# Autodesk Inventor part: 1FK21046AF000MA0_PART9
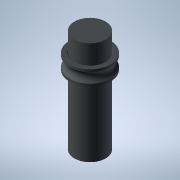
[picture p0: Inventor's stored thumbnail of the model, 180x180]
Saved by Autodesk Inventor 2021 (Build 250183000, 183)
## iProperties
Created: 2025-04
Part Number: 1FK21046AF000MA0_PART9
Material: Generic
Catalog Web Link: www.3dfindit.com
Description: -Servo synchronous motor
Document SubType Name: Modeling
Designer: psAdmin
Mass: 18.6788 g
Surface Area: 52.316 cm^2
Volume: 18.6788 cm^3
Density: 1 g/cm^3
Appearance: PSOLRGB-212-217-219
Category: PARTsolutions
Title: 1FK21046AF000MA0_PART9
Author: Cadenas PARTsolutions
Comments: Servo synchronous motor
Sending System: PARTsolutions
Preprocessor: ST-DEVELOPER v19.3
PSOL_IDENT_0: {$CADENAS_DATA/23d-libs/siemens_ag/_cat_/1c/1f/1fk21046af000ma0.prj},213 {VTYP=3D},{NB=1FK21046AF000
PSOL_IDENT_1: MA0_PART9},{LINA=1FK21046AF000MA0_PART9},{NN=1FK21046AF000MA0_PART9},{NOPRJ=TRUE},{DATE=19.08.2025 1
PSOL_IDENT_2: 4:00:28},{GEOMDATE=30.07.2025 02:02:08},{VERSION=},{LINEID=10},{WBVAR=},{WBNUMERIC=}  {NB=1FK21046AF
PSOL_IDENT_3: 000MA0_PART9},{LINA=1FK21046AF000MA0_PART9},{KT=DUMMY},{PREVIEW=../../../_pool_/cb/72/p_d211_xx_0043
PSOL_IDENT_4: 4j.png},{DESCSHORT=SIMOTICS S-1FK2 HD, SINAMICS S210 3AC 400V-480V, 3.2 Nm, 3000 rpm},{DESCLONG=SIMO
PSOL_IDENT_5: TICS S-1FK2 HD servo motor M0=3.2 Nm; PN = 1 kW at nN=3000 rpm (380-480 V); PN = 0.5 kW at nN=1500 r
PSOL_IDENT_6: pm (200-240 V); degree of protection IP64; cylindrical shaft D19x40mm; absolute encoder 22-bit + 12-
PSOL_IDENT_7: bit multiturn (encoder AM22DQC); with OCC interface; plug size M17, rotatable; SIMOTICS S-1FK2 servo
PSOL_IDENT_8: motorfor a wide range of uses in industrial environments. SIMOTICS S‑1FK2 servomotors are compact sy
PSOL_IDENT_9: nchronous motors with a high dynamic performance that set themselves apart as a result of their high
PSOL_IDENT_10: power density, degree of protection and overload capability. The motors are available in two varian
PSOL_IDENT_11: ts: as High Dynamic variant (highest dynamic performance as a result of the low intrinsic moment of
PSOL_IDENT_12: inertia for applications demanding a high dynamic performance with low moved masses) - and as Compac
PSOL_IDENT_13: t variant (precise and stable closed-loop control for medium up to large moved masses as a result of
PSOL_IDENT_14: a medium intrinsic moment of inertia). SIMOTICSS‑1FK2 servomotors fully exploit their strengths in
PSOL_IDENT_15: a system with the SINAMICSS210 frequency converter and simple connection using the one cable connect
PSOL_IDENT_16: ion (OCC). Advantages include the short control and positioning times, fast and precise correction o
PSOL_IDENT_17: f disturbing quantities as well as stable control with a high dynamic performance. The servo motors
PSOL_IDENT_18: can be configured to address a wide range of requirements. For example with and without holding brak
PSOL_IDENT_19: e, IP64 or IP65 degree of protection, singleturn or multiturn absolute encoders - to name just a few
PSOL_IDENT_20: . Further, the servomotors are available in different shaft heights extending from 20 to 100. A shaf
PSOL_IDENT_21: t sealing ring is available to achieve an IP65 degree of protection and for subsequent mounting at t
PSOL_IDENT_22: he motor or as spare part. SIMOTICS - the optimum motor for each and every motion control applicatio
PSOL_IDENT_23: n.},{INTNO=195125049666},{SUPPLIERALTNO=1FK2104-6AF00-0MA0},{MANUID=1FK21046AF000MA0},{MANUNAME=Siem
PSOL_IDENT_24: ens},{MANUTYPEDESC=Synchronous motor 1FK2-HD 3.2 NM},{AAU732=SIMOTICS},{AAO057=S-1FK2},{AAU734=SIMOT
PSOL_IDENT_25: ICS S-1FK2 HD servo motor M0=3.2 Nm; PN = 1 kW at nN=3000 rpm (380-480 V); PN = 0.5 kW at nN=1500 rp
PSOL_IDENT_26: m (200-240 V); degree of protection IP64; cylindrical shaft D19x40mm; absolute encoder 22-bit + 12-b
PSOL_IDENT_27: it multiturn (encoder AM22DQC); with OCC interface; plug size M17, rotatable;},{AAW338=Synchronous m
PSOL_IDENT_28: otor 1FK2-HD 3.2 NM},{AAO742=SIMOTICS},{AAO663=4042948694374},{NOCUPEROU=1},{PRICEQUANTITY=1},{QUANT
PSOL_IDENT_29: ITYMIN=1},{QUANTITYINT=1},{CTN=85015220},{COO=DE},{AAO676=1FK2104-6AF00-0MA0},{AAO677=Siemens AG},{O
PSOL_IDENT_30: RDERUNIT=C62},{CONTENTUNIT=C62}
NB: 1FK21046AF000MA0_PART9
NT: Servo synchronous motor
NBSYN: $MANUID._PART9
LINA: 1FK21046AF000MA0_PART9
CATALOG: SIEMENS
PREVIEW: ../../../_pool_/cb/72/p_d211_xx_00434j.png
DESCSHORT: SIMOTICS S-1FK2 HD, SINAMICS S210 3AC 400V-480V, 3.2 Nm, 3000 rpm
DESCLONG: SIMOTICS S-1FK2 HD servo motor M0=3.2 Nm; PN = 1 kW at nN=3000 rpm (380-480 V); PN = 0.5 kW at nN=1500 rpm (200-240 V); degree of protection IP64; cylindrical s
INTNO: 195125049666
SUPPLIERALTNO: 1FK2104-6AF00-0MA0
MANUID: 1FK21046AF000MA0
MANUNAME: Siemens
MANUTYPEDESC: Synchronous motor 1FK2-HD 3.2 NM
AAU732: SIMOTICS
AAO057: S-1FK2
AAU734: SIMOTICS S-1FK2 HD servo motor M0=3.2 Nm; PN = 1 kW at nN=3000 rpm (380-480 V); PN = 0.5 kW at nN=1500 rpm (200-240 V); degree of protection IP64; cylindrical s
AAW338: Synchronous motor 1FK2-HD 3.2 NM
AAO742: SIMOTICS
AAO663: 4042948694374.0
NOCUPEROU: 1
PRICEQUANTITY: 1
QUANTITYMIN: 1
QUANTITYINT: 1
CTN: 85015220
COO: DE
ARTICLENO: 1FK21046AF000MA0_PART9
BOMINFO: 1FK21046AF000MA0_PART9
CREATOR: CADENAS GmbH
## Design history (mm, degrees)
feature "2025_04_17_15_39_11_0412"
body "Solid1"
